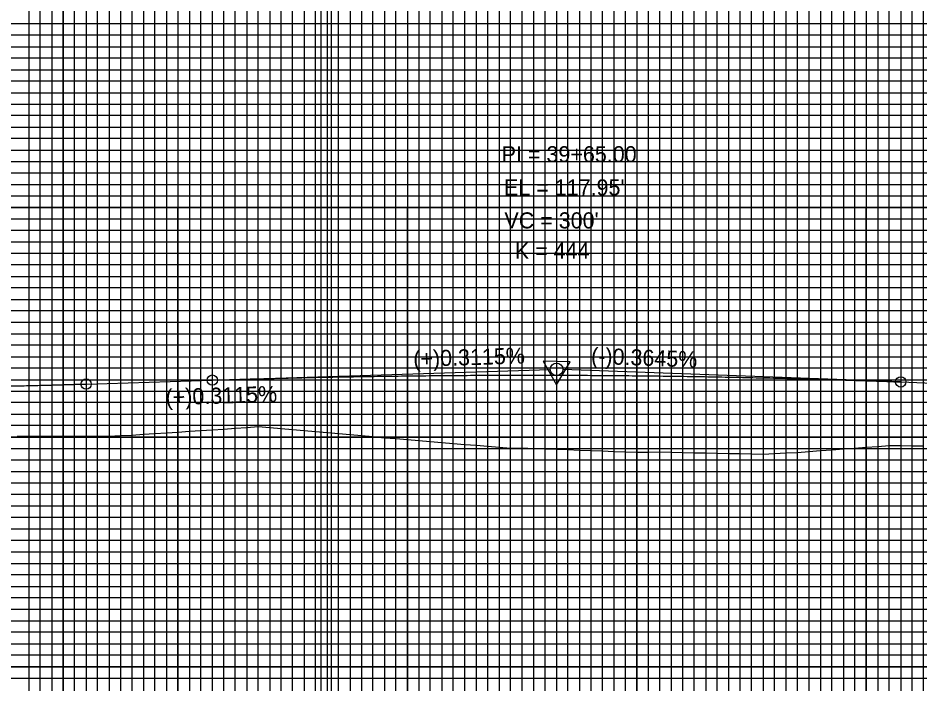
# Model space of a CAD drawing. Extents: x 2345490 to 2436403, y 465165 to 573888.
# Drawn here: x 2384497.1 to 2384890.2, y 500850.3 to 501140.3 of the extents above; entities that cross this region are included whole.
import ezdxf

# ---------------------------------------------------------------- set-up
doc = ezdxf.new("R2010")
doc.units = 0
for name, color, linetype in [('Old_Level_1', 7, 'Continuous'), ('Old_Level_18', 7, 'Continuous'), ('Old_Level_2', 7, 'Continuous'), ('Old_Level_41', 7, 'Continuous'), ('Old_Level_42', 7, 'Continuous'), ('Old_Level_43', 7, 'Continuous'), ('Old_Level_50', 7, 'Continuous'), ('Old_Level_51', 7, 'Continuous'), ('Old_Level_57', 7, 'Continuous')]:
    doc.layers.add(name, color=color, linetype=linetype)

msp = doc.modelspace()

# ---------------------------------------------------------------- linework, layer by layer
at = {"layer": 'Old_Level_1'}
for points in [[(2384496.7988, 500958.11585), (2384501.7988, 500958.1288), (2384506.7988, 500958.14175), (2384511.7988, 500958.15471), (2384516.7988, 500958.16766), (2384521.7988, 500958.18061), (2384526.7988, 500958.19356), (2384531.7988, 500958.20651), (2384536.7988, 500958.21946), (2384541.7988, 500958.4238), (2384546.7988, 500958.69079), (2384551.7988, 500959.01562), (2384556.7988, 500959.34044), (2384561.7988, 500959.66527), (2384566.7988, 500959.9901), (2384571.7988, 500960.31493), (2384576.7988, 500960.63976), (2384581.7988, 500960.96459), (2384586.7988, 500961.28941), (2384591.7988, 500961.61424), (2384596.7988, 500961.93907), (2384601.7988, 500962.37508), (2384606.7988, 500961.94067), (2384611.7988, 500961.50626), (2384616.7988, 500961.07184), (2384621.7988, 500960.63743), (2384626.7988, 500960.20302), (2384631.7988, 500959.76861), (2384636.7988, 500959.3342), (2384641.7988, 500958.89979), (2384646.7988, 500958.44945), (2384651.7988, 500957.99625), (2384656.7988, 500957.52905), (2384661.7988, 500957.09631), (2384666.7988, 500956.68181), (2384671.7988, 500956.26731), (2384676.7988, 500955.8528), (2384681.7988, 500955.4383), (2384686.7988, 500955.0238), (2384691.7988, 500954.6093), (2384696.7988, 500954.19479), (2384701.7988, 500953.78029), (2384706.7988, 500953.36579), (2384711.7988, 500952.98989), (2384716.7988, 500953.04582), (2384721.7988, 500952.87645), (2384726.7988, 500952.69102), (2384731.7988, 500952.50558), (2384736.7988, 500952.32015), (2384741.7988, 500952.13471), (2384746.7988, 500951.94927), (2384751.7988, 500951.76384), (2384756.7988, 500951.5784), (2384761.7988, 500951.39297), (2384766.7988, 500951.21879)], [(2384766.7988, 500951.21879), (2384771.7988, 500951.26086), (2384776.7988, 500951.30294), (2384781.7988, 500951.20314), (2384786.7988, 500951.10048), (2384791.7988, 500950.99782), (2384796.7988, 500950.89516), (2384801.7988, 500950.7925), (2384806.7988, 500950.68984), (2384811.7988, 500950.58718), (2384816.7988, 500950.48453), (2384821.7988, 500950.38775), (2384826.7988, 500950.63315), (2384831.7988, 500950.87855), (2384836.7988, 500951.12744), (2384841.7988, 500951.50151), (2384846.7988, 500951.87558), (2384851.7988, 500952.24965), (2384856.7988, 500952.62372), (2384861.7988, 500952.99779), (2384866.7988, 500953.37186), (2384871.7988, 500953.74593), (2384876.7988, 500954.12), (2384881.7988, 500954.08204), (2384886.7988, 500954.03754), (2384891.7988, 500953.99303)]]:
    msp.add_lwpolyline(points, dxfattribs=at)
at = {"layer": 'Old_Level_18'}
for points in [[(2384616.79875, 501632.775), (2383116.79875, 501632.775), (2383116.79875, 500582.775), (2384616.79875, 500582.775)], [(2386016.79875, 501632.775), (2384516.79875, 501632.775), (2384516.79875, 500582.775), (2386016.79875, 500582.775)]]:
    msp.add_lwpolyline(points, close=True, dxfattribs=at)
at = {"layer": 'Old_Level_2'}
for p, q in [((2384581.7988, 500982.60287), (2384729.05013, 500987.18939)), ((2384881.7988, 500981.80771), (2384734.54698, 500987.17483)), ((2384526.7988, 500980.88975), (2384581.7988, 500982.60287)), ((2384881.7988, 500981.80771), (2385266.7988, 500967.775)), ((2384526.799, 500980.89), (2384429.54775, 500977.86075))]:
    msp.add_line(p, q, dxfattribs=at)
msp.add_lwpolyline([(2384726.03436, 500990.79557), (2384731.72386, 500980.52348), (2384737.73702, 500990.56546)], close=True, dxfattribs=at)
for centre, radius in [((2384731.7988, 500987.275), 2.75), ((2384526.7988, 500980.88975), 2.25), ((2384526.799, 500980.89), 2.25), ((2384581.7988, 500982.60287), 2.25), ((2384881.7988, 500981.80771), 2.25)]:
    msp.add_circle(centre, radius, dxfattribs=at)
for points in [[(2384326.799, 500981.54875), (2384330.799, 500981.4005), (2384334.799, 500981.25775), (2384338.799, 500981.12075), (2384342.799, 500980.989), (2384346.799, 500980.863), (2384350.799, 500980.74225), (2384354.799, 500980.627), (2384358.799, 500980.5175), (2384362.799, 500980.4135), (2384366.799, 500980.31475), (2384370.799, 500980.22175), (2384374.799, 500980.13425), (2384378.799, 500980.052), (2384382.799, 500979.9755), (2384386.799, 500979.9045), (2384390.799, 500979.839), (2384394.799, 500979.779), (2384398.799, 500979.7245), (2384402.799, 500979.6755), (2384406.799, 500979.632), (2384410.799, 500979.594), (2384414.799, 500979.5615), (2384418.799, 500979.5345), (2384422.799, 500979.51325), (2384426.799, 500979.49725), (2384430.799, 500979.48675), (2384434.799, 500979.482), (2384438.799, 500979.4825), (2384442.799, 500979.4885), (2384446.799, 500979.50025), (2384450.799, 500979.51725), (2384454.799, 500979.54), (2384458.799, 500979.56825), (2384462.799, 500979.60175), (2384466.799, 500979.641), (2384470.799, 500979.68575), (2384474.799, 500979.73575), (2384478.799, 500979.7915), (2384482.799, 500979.85275), (2384486.799, 500979.9195), (2384490.799, 500979.99175), (2384494.799, 500980.0695), (2384498.799, 500980.15275), (2384502.799, 500980.2415), (2384506.799, 500980.33575), (2384510.799, 500980.4355), (2384514.799, 500980.541), (2384518.799, 500980.65175), (2384522.799, 500980.768), (2384526.799, 500980.89)], [(2384581.7988, 500982.60287), (2384587.7988, 500982.7857), (2384593.7988, 500982.96042), (2384599.7988, 500983.12702), (2384605.7988, 500983.28552), (2384611.7988, 500983.4359), (2384617.7988, 500983.57817), (2384623.7988, 500983.71233), (2384629.7988, 500983.83838), (2384635.7988, 500983.95632), (2384641.7988, 500984.06614), (2384647.7988, 500984.16786), (2384653.7988, 500984.26146), (2384659.7988, 500984.34695), (2384665.7988, 500984.42433), (2384671.7988, 500984.4936), (2384677.7988, 500984.55476), (2384683.7988, 500984.6078), (2384689.7988, 500984.65273), (2384695.7988, 500984.68956), (2384701.7988, 500984.71827), (2384707.7988, 500984.73887), (2384713.7988, 500984.75135), (2384719.7988, 500984.75573), (2384725.7988, 500984.75199), (2384731.7988, 500984.74014), (2384737.7988, 500984.72019), (2384743.7988, 500984.69212), (2384749.7988, 500984.65593), (2384755.7988, 500984.61164), (2384761.7988, 500984.55923), (2384767.7988, 500984.49872), (2384773.7988, 500984.43009), (2384779.7988, 500984.35335), (2384785.7988, 500984.2685), (2384791.7988, 500984.17554), (2384797.7988, 500984.07446), (2384803.7988, 500983.96528), (2384809.7988, 500983.84798), (2384815.7988, 500983.72257), (2384821.7988, 500983.58905), (2384827.7988, 500983.44742), (2384833.7988, 500983.29767), (2384839.7988, 500983.13982), (2384845.7988, 500982.97385), (2384851.7988, 500982.79977), (2384857.7988, 500982.61758), (2384863.7988, 500982.42728), (2384869.7988, 500982.22887), (2384875.7988, 500982.02235), (2384881.7988, 500981.80771)]]:
    msp.add_spline(points, degree=3, dxfattribs=at)
at = {"layer": 'Old_Level_41'}
for points in [[(2384516.79875, 501632.775), (2384566.79875, 501632.775), (2384566.79875, 500607.775), (2384616.79875, 500607.775), (2384616.79875, 501632.775), (2384666.79875, 501632.775), (2384666.79875, 500607.775), (2384716.79875, 500607.775), (2384716.79875, 501632.775), (2384766.79875, 501632.775), (2384766.79875, 500607.775), (2384816.79875, 500607.775), (2384816.79875, 501632.775), (2384866.79875, 501632.775), (2384866.79875, 500607.775), (2384916.79875, 500607.775), (2384916.79875, 501632.775), (2384966.79875, 501632.775), (2384966.79875, 500607.775), (2385016.79875, 500607.775), (2385016.79875, 501632.775), (2385066.79875, 501632.775), (2385066.79875, 500607.775), (2385116.79875, 500607.775)], [(2384591.79875, 500607.775), (2384591.79875, 501632.775), (2384641.79875, 501632.775), (2384641.79875, 500607.775), (2384691.79875, 500607.775), (2384691.79875, 501632.775), (2384741.79875, 501632.775), (2384741.79875, 500607.775), (2384791.79875, 500607.775), (2384791.79875, 501632.775), (2384841.79875, 501632.775), (2384841.79875, 500607.775), (2384891.79875, 500607.775), (2384891.79875, 501632.775), (2384941.79875, 501632.775), (2384941.79875, 500607.775), (2384991.79875, 500607.775), (2384991.79875, 501632.775), (2385041.79875, 501632.775), (2385041.79875, 500607.775), (2385091.79875, 500607.775), (2385091.79875, 501632.775), (2385141.79875, 501632.775)], [(2384541.79875, 501495.225), (2384541.79875, 500607.775)], [(2384616.79875, 501132.775), (2383116.79875, 501132.775), (2383116.79875, 501082.775), (2384616.79875, 501082.775)], [(2386016.79875, 501132.775), (2384516.79875, 501132.775), (2384516.79875, 501082.775), (2386016.79875, 501082.775)], [(2384616.79875, 501032.775), (2383116.79875, 501032.775), (2383116.79875, 500982.775), (2384616.79875, 500982.775)], [(2386016.79875, 501032.775), (2384516.79875, 501032.775), (2384516.79875, 500982.775), (2386016.79875, 500982.775)], [(2384616.79875, 500957.775), (2383116.79875, 500957.775), (2383116.79875, 501007.775), (2384616.79875, 501007.775)], [(2386016.79875, 500957.775), (2384516.79875, 500957.775), (2384516.79875, 501007.775), (2386016.79875, 501007.775)], [(2384616.79875, 500932.775), (2383116.79875, 500932.775), (2383116.79875, 500882.775), (2384616.79875, 500882.775)], [(2386016.79875, 500932.775), (2384516.79875, 500932.775), (2384516.79875, 500882.775), (2386016.79875, 500882.775)], [(2384616.79875, 500857.775), (2383116.79875, 500857.775), (2383116.79875, 500907.775), (2384616.79875, 500907.775)], [(2386016.79875, 500857.775), (2384516.79875, 500857.775), (2384516.79875, 500907.775), (2386016.79875, 500907.775)]]:
    msp.add_lwpolyline(points, dxfattribs=at)
at = {"layer": 'Old_Level_42'}
for points in [[(2384466.79875, 501495.225), (2384466.79875, 500607.775), (2384516.79875, 500607.775), (2384516.79875, 501495.225)], [(2384566.79875, 501495.225), (2384566.79875, 500607.775), (2384616.79875, 500607.775)], [(2384616.79875, 501057.775), (2383116.79875, 501057.775), (2383116.79875, 501107.775), (2384616.79875, 501107.775)], [(2386016.79875, 501057.775), (2384516.79875, 501057.775), (2384516.79875, 501107.775), (2386016.79875, 501107.775)]]:
    msp.add_lwpolyline(points, dxfattribs=at)
at = {"layer": 'Old_Level_43'}
for points in [[(2384571.79875, 501632.775), (2384571.79875, 500607.775), (2384576.79875, 500607.775), (2384576.79875, 501632.775)], [(2384581.79875, 501632.775), (2384581.79875, 500607.775), (2384586.79875, 500607.775), (2384586.79875, 501632.775)], [(2384596.79875, 501632.775), (2384596.79875, 500607.775), (2384601.79875, 500607.775), (2384601.79875, 501632.775)], [(2384606.79875, 501632.775), (2384606.79875, 500607.775), (2384611.79875, 500607.775), (2384611.79875, 501632.775)], [(2384621.79875, 501632.775), (2384621.79875, 500607.775), (2384626.79875, 500607.775), (2384626.79875, 501632.775)], [(2384631.79875, 501632.775), (2384631.79875, 500607.775), (2384636.79875, 500607.775), (2384636.79875, 501632.775)], [(2384646.79875, 501632.775), (2384646.79875, 500607.775), (2384651.79875, 500607.775), (2384651.79875, 501632.775)], [(2384656.79875, 501632.775), (2384656.79875, 500607.775), (2384661.79875, 500607.775), (2384661.79875, 501632.775)], [(2384671.79875, 501632.775), (2384671.79875, 500607.775), (2384676.79875, 500607.775), (2384676.79875, 501632.775)], [(2384681.79875, 501632.775), (2384681.79875, 500607.775), (2384686.79875, 500607.775), (2384686.79875, 501632.775)], [(2384696.79875, 501632.775), (2384696.79875, 500607.775), (2384701.79875, 500607.775), (2384701.79875, 501632.775)], [(2384706.79875, 501632.775), (2384706.79875, 500607.775), (2384711.79875, 500607.775), (2384711.79875, 501632.775)], [(2384721.79875, 501632.775), (2384721.79875, 500607.775), (2384726.79875, 500607.775), (2384726.79875, 501632.775)], [(2384731.79875, 500607.775), (2384736.79875, 500607.775), (2384736.79875, 501632.775)], [(2384731.79875, 501632.775), (2384731.79875, 500607.775)], [(2384746.79875, 501632.775), (2384746.79875, 500607.775), (2384751.79875, 500607.775), (2384751.79875, 501632.775)], [(2384756.79875, 501632.775), (2384756.79875, 500607.775), (2384761.79875, 500607.775), (2384761.79875, 501632.775)], [(2384771.79875, 501632.775), (2384771.79875, 500607.775), (2384776.79875, 500607.775), (2384776.79875, 501632.775)], [(2384781.79875, 501632.775), (2384781.79875, 500607.775), (2384786.79875, 500607.775), (2384786.79875, 501632.775)], [(2384796.79875, 501632.775), (2384796.79875, 500607.775), (2384801.79875, 500607.775), (2384801.79875, 501632.775)], [(2384806.79875, 501632.775), (2384806.79875, 500607.775), (2384811.79875, 500607.775), (2384811.79875, 501632.775)], [(2384821.79875, 501632.775), (2384821.79875, 500607.775), (2384826.79875, 500607.775), (2384826.79875, 501632.775)], [(2384831.79875, 501632.775), (2384831.79875, 500607.775), (2384836.79875, 500607.775), (2384836.79875, 501632.775)], [(2384846.79875, 501632.775), (2384846.79875, 500607.775), (2384851.79875, 500607.775), (2384851.79875, 501632.775)], [(2384856.79875, 501632.775), (2384856.79875, 500607.775), (2384861.79875, 500607.775), (2384861.79875, 501632.775)], [(2384871.79875, 501632.775), (2384871.79875, 500607.775), (2384876.79875, 500607.775), (2384876.79875, 501632.775)], [(2384881.79875, 501632.775), (2384881.79875, 500607.775), (2384886.79875, 500607.775), (2384886.79875, 501632.775)], [(2384501.79875, 501495.225), (2384501.79875, 500607.775)], [(2384501.79875, 500607.775), (2384506.79875, 500607.775), (2384506.79875, 501495.225)], [(2384511.79875, 501495.225), (2384511.79875, 500607.775), (2384521.79875, 500607.775), (2384521.79875, 501495.225)], [(2384526.79875, 501495.225), (2384526.79875, 500607.775), (2384531.79875, 500607.775), (2384531.79875, 501495.225)], [(2384536.79875, 501495.225), (2384536.79875, 500607.775), (2384546.79875, 500607.775), (2384546.79875, 501495.225)], [(2384551.79875, 501495.225), (2384551.79875, 500607.775), (2384556.79875, 500607.775), (2384556.79875, 501495.225)], [(2384561.79875, 501495.225), (2384561.79875, 500607.775), (2384571.79875, 500607.775)], [(2384566.79875, 501137.775), (2383166.79875, 501137.775), (2383166.79875, 501127.775), (2384566.79875, 501127.775)], [(2385966.79875, 501137.775), (2384566.79875, 501137.775), (2384566.79875, 501127.775), (2385966.79875, 501127.775)], [(2384566.79875, 501122.775), (2383166.79875, 501122.775), (2383166.79875, 501117.775), (2384566.79875, 501117.775)], [(2385966.79875, 501122.775), (2384566.79875, 501122.775), (2384566.79875, 501117.775), (2385966.79875, 501117.775)], [(2384566.79875, 501112.775), (2383166.79875, 501112.775)], [(2385966.79875, 501112.775), (2384566.79875, 501112.775)], [(2383166.79875, 501102.775), (2384566.79875, 501102.775)], [(2384566.79875, 501102.775), (2385966.79875, 501102.775)], [(2384566.79875, 501097.775), (2383166.79875, 501097.775), (2383166.79875, 501092.775), (2384566.79875, 501092.775)], [(2385966.79875, 501097.775), (2384566.79875, 501097.775), (2384566.79875, 501092.775), (2385966.79875, 501092.775)], [(2384566.79875, 501087.775), (2383166.79875, 501087.775), (2383166.79875, 501077.775), (2384566.79875, 501077.775)], [(2385966.79875, 501087.775), (2384566.79875, 501087.775), (2384566.79875, 501077.775), (2385966.79875, 501077.775)], [(2384566.79875, 501072.775), (2383166.79875, 501072.775), (2383166.79875, 501067.775), (2384566.79875, 501067.775)], [(2385966.79875, 501072.775), (2384566.79875, 501072.775), (2384566.79875, 501067.775), (2385966.79875, 501067.775)], [(2384566.79875, 501062.775), (2383166.79875, 501062.775), (2383166.79875, 501052.775), (2384566.79875, 501052.775)], [(2385966.79875, 501062.775), (2384566.79875, 501062.775), (2384566.79875, 501052.775), (2385966.79875, 501052.775)], [(2384566.79875, 501047.775), (2383166.79875, 501047.775), (2383166.79875, 501042.775), (2384566.79875, 501042.775)], [(2385966.79875, 501047.775), (2384566.79875, 501047.775), (2384566.79875, 501042.775), (2385966.79875, 501042.775)], [(2384566.79875, 501037.775), (2383166.79875, 501037.775), (2383166.79875, 501027.775), (2384566.79875, 501027.775)], [(2385966.79875, 501037.775), (2384566.79875, 501037.775), (2384566.79875, 501027.775), (2385966.79875, 501027.775)], [(2384566.79875, 501022.775), (2383166.79875, 501022.775), (2383166.79875, 501017.775), (2384566.79875, 501017.775)], [(2385966.79875, 501022.775), (2384566.79875, 501022.775), (2384566.79875, 501017.775), (2385966.79875, 501017.775)], [(2384566.79875, 501012.775), (2383166.79875, 501012.775), (2383166.79875, 501002.775), (2384566.79875, 501002.775)], [(2385966.79875, 501012.775), (2384566.79875, 501012.775), (2384566.79875, 501002.775), (2385966.79875, 501002.775)], [(2384566.79875, 500997.775), (2383166.79875, 500997.775), (2383166.79875, 500992.775), (2384566.79875, 500992.775)], [(2385966.79875, 500997.775), (2384566.79875, 500997.775), (2384566.79875, 500992.775), (2385966.79875, 500992.775)], [(2384566.79875, 500987.775), (2383166.79875, 500987.775), (2383166.79875, 500977.775), (2384566.79875, 500977.775)], [(2385966.79875, 500987.775), (2384566.79875, 500987.775), (2384566.79875, 500977.775), (2385966.79875, 500977.775)], [(2384566.79875, 500972.775), (2383166.79875, 500972.775), (2383166.79875, 500967.775), (2384566.79875, 500967.775)], [(2385966.79875, 500972.775), (2384566.79875, 500972.775), (2384566.79875, 500967.775), (2385966.79875, 500967.775)], [(2384566.79875, 500962.775), (2383166.79875, 500962.775), (2383166.79875, 500952.775), (2384566.79875, 500952.775)], [(2385966.79875, 500962.775), (2384566.79875, 500962.775), (2384566.79875, 500952.775), (2385966.79875, 500952.775)], [(2384566.79875, 500947.775), (2383166.79875, 500947.775), (2383166.79875, 500942.775), (2384566.79875, 500942.775)], [(2385966.79875, 500947.775), (2384566.79875, 500947.775), (2384566.79875, 500942.775), (2385966.79875, 500942.775)], [(2384566.79875, 500937.775), (2383166.79875, 500937.775), (2383166.79875, 500927.775), (2384566.79875, 500927.775)], [(2385966.79875, 500937.775), (2384566.79875, 500937.775), (2384566.79875, 500927.775), (2385966.79875, 500927.775)], [(2384566.79875, 500922.775), (2383166.79875, 500922.775), (2383166.79875, 500917.775), (2384566.79875, 500917.775)], [(2385966.79875, 500922.775), (2384566.79875, 500922.775), (2384566.79875, 500917.775), (2385966.79875, 500917.775)], [(2384566.79875, 500912.775), (2383166.79875, 500912.775), (2383166.79875, 500902.775), (2384566.79875, 500902.775)], [(2385966.79875, 500912.775), (2384566.79875, 500912.775), (2384566.79875, 500902.775), (2385966.79875, 500902.775)], [(2384566.79875, 500897.775), (2383166.79875, 500897.775), (2383166.79875, 500892.775), (2384566.79875, 500892.775)], [(2385966.79875, 500897.775), (2384566.79875, 500897.775), (2384566.79875, 500892.775), (2385966.79875, 500892.775)], [(2384566.79875, 500887.775), (2383166.79875, 500887.775), (2383166.79875, 500877.775), (2384566.79875, 500877.775)], [(2385966.79875, 500887.775), (2384566.79875, 500887.775), (2384566.79875, 500877.775), (2385966.79875, 500877.775)], [(2384566.79875, 500872.775), (2383166.79875, 500872.775), (2383166.79875, 500867.775), (2384566.79875, 500867.775)], [(2385966.79875, 500872.775), (2384566.79875, 500872.775), (2384566.79875, 500867.775), (2385966.79875, 500867.775)], [(2384566.79875, 500862.775), (2383166.79875, 500862.775), (2383166.79875, 500852.775), (2384566.79875, 500852.775)], [(2385966.79875, 500862.775), (2384566.79875, 500862.775), (2384566.79875, 500852.775), (2385966.79875, 500852.775)]]:
    msp.add_lwpolyline(points, dxfattribs=at)
at = {"layer": 'Old_Level_50'}
msp.add_lwpolyline([(2384629.29875, 501635.325), (2382962.79875, 501635.325), (2382962.79875, 500580.225), (2384629.29875, 500580.225)], close=True, dxfattribs=at)
at = {"layer": 'Old_Level_51'}
msp.add_lwpolyline([(2384633.79875, 501657.775), (2382949.79875, 501657.775), (2382949.79875, 500557.775), (2384633.79875, 500557.775)], close=True, dxfattribs=at)
at = {"layer": 'Old_Level_57'}
for p, q in [((2381716.79925, 501057.77525), (2385066.79875, 501057.77525)), ((2384566.79875, 500607.77525), (2384566.79875, 501057.77525)), ((2384566.79875, 500607.87525), (2384566.79875, 501057.77525)), ((2384666.79875, 500607.77525), (2384666.79875, 501057.77525)), ((2384666.79875, 500607.87525), (2384666.79875, 501057.77525)), ((2384766.79875, 500607.77525), (2384766.79875, 501057.77525)), ((2384766.79875, 500607.87525), (2384766.79875, 501057.77525)), ((2384866.79875, 500607.77525), (2384866.79875, 501057.77525)), ((2384866.79875, 500607.87525), (2384866.79875, 501057.77525)), ((2381716.79925, 501007.77525), (2385066.79875, 501007.77525)), ((2381716.79925, 500957.77525), (2385066.79875, 500957.77525)), ((2381716.79925, 500907.77525), (2385066.79875, 500907.77525)), ((2381716.79925, 500857.77525), (2385066.79875, 500857.77525))]:
    msp.add_line(p, q, dxfattribs=at)

# ---------------------------------------------------------------- texts
at = {"layer": 'Old_Level_2'}
for s, height, p in [('PI = 39+65.00', 7.0000005, (2384707.90069, 501077.47397)), ("EL = 117.95'", 7.0000005, (2384708.90995, 501063.02491)), ("VC = 300'", 7, (2384709.0904, 501048.66436)), ('K = 444', 7, (2384713.63208, 501035.41427))]:
    msp.add_text(s, height=height, dxfattribs=at).set_placement(p)
for s, height, rotation, p in [('(+)0.3115%', 7, 1.7840458, (2384669.47222, 500988.33514)), ('(-)0.3645%', 7, 357.9125732, (2384746.76973, 500989.73132)), ('(+)0.3115%', 7.000001, 1.7840472, (2384561.5115, 500971.62675))]:
    msp.add_text(s, height=height, rotation=rotation, dxfattribs=at).set_placement(p)

doc.saveas('drawing.dxf')
